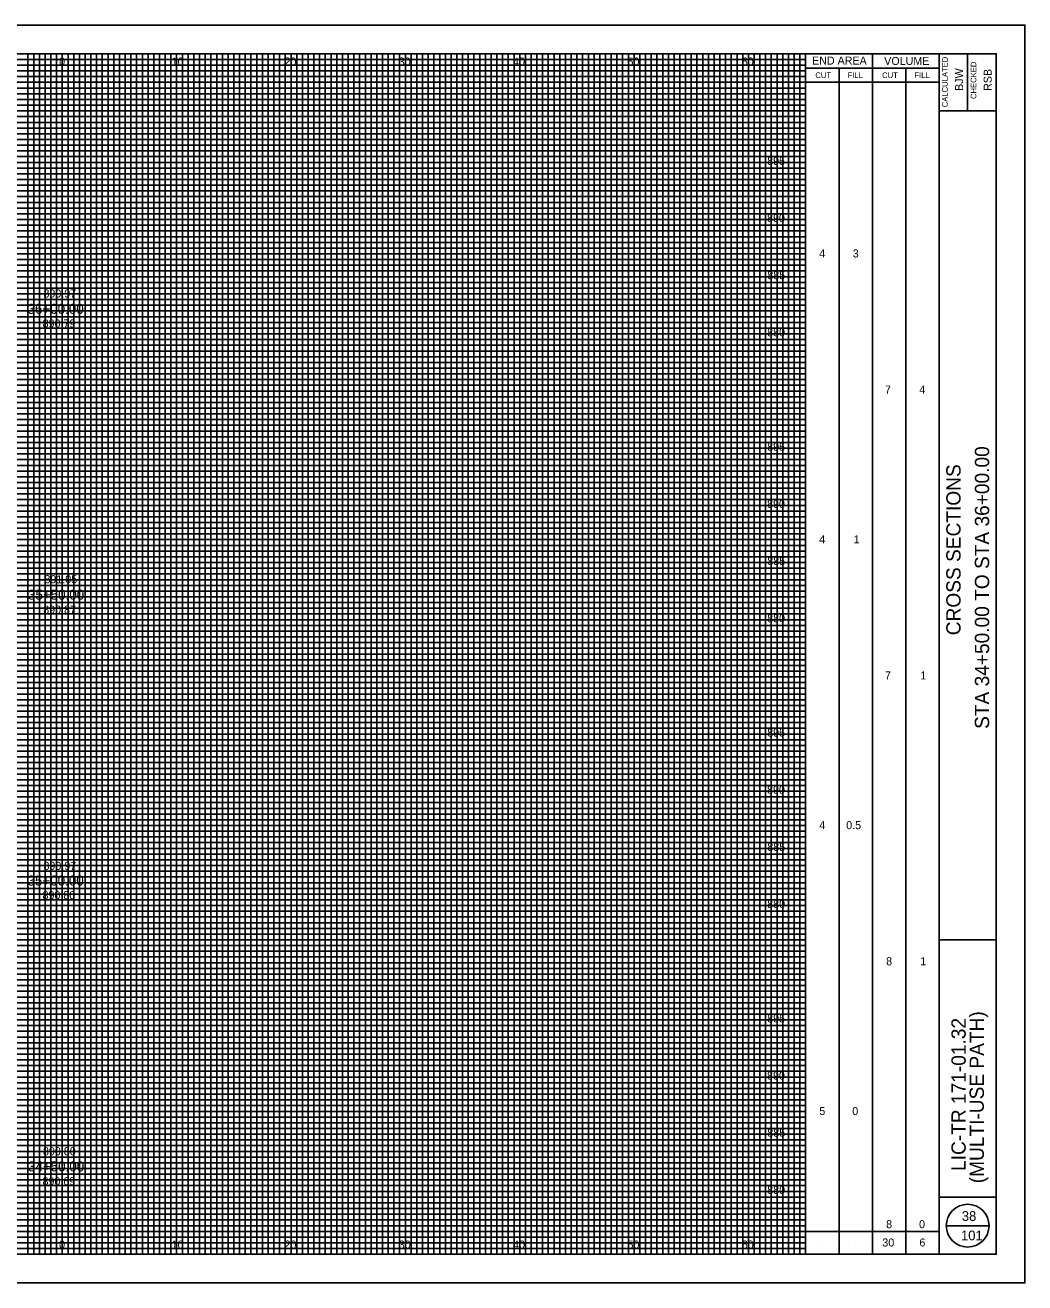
# Model space of a CAD drawing. Extents: x -10 to 160, y -2 to 2522.
# Drawn here: x 72.6 to 160, y 1147.5 to 1257.5 of the extents above; entities that cross this region are included whole.
import ezdxf

# ---------------------------------------------------------------- set-up
doc = ezdxf.new("R2010")
doc.units = 0
for name, color, linetype in [('GK_Cells', 7, 'Continuous'), ('GK_Patterns', 7, 'Continuous'), ('TX_P_10', 7, 'Continuous'), ('TX_X_10', 7, 'Continuous'), ('XS_P_Finished_Grade_Seeded', 7, 'Continuous'), ('XS_P_Pavt_Surface', 7, 'Continuous'), ('XS_P_Subgrade', 7, 'Continuous'), ('XS_X_Ground_Line', 7, 'Continuous')]:
    doc.layers.add(name, color=color, linetype=linetype)

msp = doc.modelspace()

# ---------------------------------------------------------------- linework, layer by layer
at = {"layer": 'GK_Cells'}
msp.add_lwpolyline([(-10, 1147.5), (160, 1147.5), (160, 1257.5), (-10, 1257.5)], close=True, dxfattribs=at)
at = {"layer": 'TX_P_10'}
for p, q in [((140.83, 1150), (140.83, 1255)), ((146.67, 1150), (146.67, 1255)), ((140.83, 1253.75), (152.5, 1253.75)), ((143.75, 1150), (143.75, 1253.75)), ((149.58, 1150), (149.58, 1253.75)), ((140.83, 1252.5), (152.5, 1252.5)), ((140.83, 1152), (152.5, 1152)), ((153.12, 1152.5), (156.88, 1152.5)), ((142.29, 1151), (142.29, 1151)), ((145.21, 1151), (145.21, 1151)), ((148.12, 1151), (148.12, 1151)), ((151.04, 1151), (151.04, 1151))]:
    msp.add_line(p, q, dxfattribs=at)
msp.add_circle((155, 1152.5), 1.87, dxfattribs=at)
at = {"layer": 'TX_X_10'}
for p, q in [((75.83, 1150), (75.83, 1255)), ((80.83, 1150), (80.83, 1255)), ((85.83, 1150), (85.83, 1255)), ((90.83, 1150), (90.83, 1255)), ((95.83, 1150), (95.83, 1255)), ((100.83, 1150), (100.83, 1255)), ((105.83, 1150), (105.83, 1255)), ((110.83, 1150), (110.83, 1255)), ((115.83, 1150), (115.83, 1255)), ((120.83, 1150), (120.83, 1255)), ((125.83, 1150), (125.83, 1255)), ((130.83, 1150), (130.83, 1255)), ((135.83, 1150), (135.83, 1255)), ((5.83, 1250), (140.83, 1250)), ((5.83, 1245), (140.83, 1245)), ((5.83, 1240), (140.83, 1240)), ((5.83, 1235), (140.83, 1235)), ((5.83, 1230), (140.83, 1230)), ((5.83, 1225), (140.83, 1225)), ((5.83, 1220), (140.83, 1220)), ((5.83, 1215), (140.83, 1215)), ((5.83, 1210), (140.83, 1210)), ((5.83, 1205), (140.83, 1205)), ((5.83, 1200), (140.83, 1200)), ((5.83, 1195), (140.83, 1195)), ((5.83, 1190), (140.83, 1190)), ((5.83, 1185), (140.83, 1185)), ((5.83, 1180), (140.83, 1180)), ((5.83, 1175), (140.83, 1175)), ((5.83, 1170), (140.83, 1170)), ((5.83, 1165), (140.83, 1165)), ((5.83, 1160), (140.83, 1160)), ((5.83, 1155), (140.83, 1155))]:
    msp.add_line(p, q, dxfattribs=at)
at = {"layer": 'XS_P_Pavt_Surface'}
for p, q in [((152.5, 1150), (152.5, 1255)), ((155, 1255), (155, 1250)), ((152.5, 1250), (157.5, 1250)), ((152.5, 1177.5), (157.5, 1177.5)), ((152.5, 1155), (157.5, 1155))]:
    msp.add_line(p, q, dxfattribs=at)
msp.add_lwpolyline([(0, 1255), (157.5, 1255), (157.5, 1150), (0, 1150)], close=True, dxfattribs=at)
at = {"layer": 'XS_X_Ground_Line'}
for p, q in [((5.83, 1254.5), (140.83, 1254.5)), ((5.83, 1254), (140.83, 1254)), ((72.83, 1150), (72.83, 1255)), ((73.33, 1150), (73.33, 1255)), ((73.83, 1150), (73.83, 1255)), ((74.33, 1150), (74.33, 1255)), ((74.83, 1150), (74.83, 1255)), ((75.33, 1150), (75.33, 1255)), ((76.33, 1150), (76.33, 1255)), ((76.83, 1150), (76.83, 1255)), ((77.33, 1150), (77.33, 1255)), ((77.83, 1150), (77.83, 1255)), ((78.33, 1150), (78.33, 1255)), ((78.83, 1150), (78.83, 1255)), ((79.33, 1150), (79.33, 1255)), ((79.83, 1150), (79.83, 1255)), ((80.33, 1150), (80.33, 1255)), ((81.33, 1150), (81.33, 1255)), ((81.83, 1150), (81.83, 1255)), ((82.33, 1150), (82.33, 1255)), ((82.83, 1150), (82.83, 1255)), ((83.33, 1150), (83.33, 1255)), ((83.83, 1150), (83.83, 1255)), ((84.33, 1150), (84.33, 1255)), ((84.83, 1150), (84.83, 1255)), ((85.33, 1150), (85.33, 1255)), ((86.33, 1150), (86.33, 1255)), ((86.83, 1150), (86.83, 1255)), ((87.33, 1150), (87.33, 1255)), ((87.83, 1150), (87.83, 1255)), ((88.33, 1150), (88.33, 1255)), ((88.83, 1150), (88.83, 1255)), ((89.33, 1150), (89.33, 1255)), ((89.83, 1150), (89.83, 1255)), ((90.33, 1150), (90.33, 1255)), ((91.33, 1150), (91.33, 1255)), ((91.83, 1150), (91.83, 1255)), ((92.33, 1150), (92.33, 1255)), ((92.83, 1150), (92.83, 1255)), ((93.33, 1150), (93.33, 1255)), ((93.83, 1150), (93.83, 1255)), ((94.33, 1150), (94.33, 1255)), ((94.83, 1150), (94.83, 1255)), ((95.33, 1150), (95.33, 1255)), ((96.33, 1150), (96.33, 1255)), ((96.83, 1150), (96.83, 1255)), ((97.33, 1150), (97.33, 1255)), ((97.83, 1150), (97.83, 1255)), ((98.33, 1150), (98.33, 1255)), ((98.83, 1150), (98.83, 1255)), ((99.33, 1150), (99.33, 1255)), ((99.83, 1150), (99.83, 1255)), ((100.33, 1150), (100.33, 1255)), ((101.33, 1150), (101.33, 1255)), ((101.83, 1150), (101.83, 1255)), ((102.33, 1150), (102.33, 1255)), ((102.83, 1150), (102.83, 1255)), ((103.33, 1150), (103.33, 1255)), ((103.83, 1150), (103.83, 1255)), ((104.33, 1150), (104.33, 1255)), ((104.83, 1150), (104.83, 1255)), ((105.33, 1150), (105.33, 1255)), ((106.33, 1150), (106.33, 1255)), ((106.83, 1150), (106.83, 1255)), ((107.33, 1150), (107.33, 1255)), ((107.83, 1150), (107.83, 1255)), ((108.33, 1150), (108.33, 1255)), ((108.83, 1150), (108.83, 1255)), ((109.33, 1150), (109.33, 1255)), ((109.83, 1150), (109.83, 1255)), ((110.33, 1150), (110.33, 1255)), ((111.33, 1150), (111.33, 1255)), ((111.83, 1150), (111.83, 1255)), ((112.33, 1150), (112.33, 1255)), ((112.83, 1150), (112.83, 1255)), ((113.33, 1150), (113.33, 1255)), ((113.83, 1150), (113.83, 1255)), ((114.33, 1150), (114.33, 1255)), ((114.83, 1150), (114.83, 1255)), ((115.33, 1150), (115.33, 1255)), ((116.33, 1150), (116.33, 1255)), ((116.83, 1150), (116.83, 1255)), ((117.33, 1150), (117.33, 1255)), ((117.83, 1150), (117.83, 1255)), ((118.33, 1150), (118.33, 1255)), ((118.83, 1150), (118.83, 1255)), ((119.33, 1150), (119.33, 1255)), ((119.83, 1150), (119.83, 1255)), ((120.33, 1150), (120.33, 1255)), ((121.33, 1150), (121.33, 1255)), ((121.83, 1150), (121.83, 1255)), ((122.33, 1150), (122.33, 1255)), ((122.83, 1150), (122.83, 1255)), ((123.33, 1150), (123.33, 1255)), ((123.83, 1150), (123.83, 1255)), ((124.33, 1150), (124.33, 1255)), ((124.83, 1150), (124.83, 1255)), ((125.33, 1150), (125.33, 1255)), ((126.33, 1150), (126.33, 1255)), ((126.83, 1150), (126.83, 1255)), ((127.33, 1150), (127.33, 1255)), ((127.83, 1150), (127.83, 1255)), ((128.33, 1150), (128.33, 1255)), ((128.83, 1150), (128.83, 1255)), ((129.33, 1150), (129.33, 1255)), ((129.83, 1150), (129.83, 1255)), ((130.33, 1150), (130.33, 1255)), ((131.33, 1150), (131.33, 1255)), ((131.83, 1150), (131.83, 1255)), ((132.33, 1150), (132.33, 1255)), ((132.83, 1150), (132.83, 1255)), ((133.33, 1150), (133.33, 1255)), ((133.83, 1150), (133.83, 1255)), ((134.33, 1150), (134.33, 1255)), ((134.83, 1150), (134.83, 1255)), ((135.33, 1150), (135.33, 1255)), ((136.33, 1150), (136.33, 1255)), ((136.83, 1150), (136.83, 1255)), ((137.33, 1150), (137.33, 1255)), ((137.83, 1150), (137.83, 1255)), ((138.33, 1150), (138.33, 1255)), ((138.83, 1150), (138.83, 1255)), ((139.33, 1150), (139.33, 1255)), ((139.83, 1150), (139.83, 1255)), ((140.33, 1150), (140.33, 1255)), ((5.83, 1253.5), (140.83, 1253.5)), ((5.83, 1253), (140.83, 1253)), ((5.83, 1252.5), (140.83, 1252.5)), ((5.83, 1252), (140.83, 1252)), ((5.83, 1251.5), (140.83, 1251.5)), ((5.83, 1251), (140.83, 1251)), ((5.83, 1250.5), (140.83, 1250.5)), ((5.83, 1249.5), (140.83, 1249.5)), ((5.83, 1249), (140.83, 1249)), ((5.83, 1248.5), (140.83, 1248.5)), ((5.83, 1248), (140.83, 1248)), ((5.83, 1247.5), (140.83, 1247.5)), ((5.83, 1247), (140.83, 1247)), ((5.83, 1246.5), (140.83, 1246.5)), ((5.83, 1246), (140.83, 1246)), ((5.83, 1245.5), (140.83, 1245.5)), ((5.83, 1244.5), (140.83, 1244.5)), ((5.83, 1244), (140.83, 1244)), ((5.83, 1243.5), (140.83, 1243.5)), ((5.83, 1243), (140.83, 1243)), ((5.83, 1242.5), (140.83, 1242.5)), ((5.83, 1242), (140.83, 1242)), ((5.83, 1241.5), (140.83, 1241.5)), ((5.83, 1241), (140.83, 1241)), ((5.83, 1240.5), (140.83, 1240.5)), ((5.83, 1239.5), (140.83, 1239.5)), ((5.83, 1239), (140.83, 1239)), ((5.83, 1238.5), (140.83, 1238.5)), ((5.83, 1238), (140.83, 1238)), ((5.83, 1237.5), (140.83, 1237.5)), ((5.83, 1237), (140.83, 1237)), ((5.83, 1236.5), (140.83, 1236.5)), ((5.83, 1236), (140.83, 1236)), ((5.83, 1235.5), (140.83, 1235.5)), ((5.83, 1234.5), (140.83, 1234.5)), ((5.83, 1234), (140.83, 1234)), ((5.83, 1233.5), (140.83, 1233.5)), ((5.83, 1233), (140.83, 1233)), ((5.83, 1232.5), (140.83, 1232.5)), ((5.83, 1232), (140.83, 1232)), ((5.83, 1231.5), (140.83, 1231.5)), ((5.83, 1231), (140.83, 1231)), ((5.83, 1230.5), (140.83, 1230.5)), ((5.83, 1229.5), (140.83, 1229.5)), ((5.83, 1229), (140.83, 1229)), ((5.83, 1228.5), (140.83, 1228.5)), ((5.83, 1228), (140.83, 1228)), ((5.83, 1227.5), (140.83, 1227.5)), ((5.83, 1227), (140.83, 1227)), ((5.83, 1226.5), (140.83, 1226.5)), ((5.83, 1226), (140.83, 1226)), ((5.83, 1225.5), (140.83, 1225.5)), ((5.83, 1224.5), (140.83, 1224.5)), ((5.83, 1224), (140.83, 1224)), ((5.83, 1223.5), (140.83, 1223.5)), ((5.83, 1223), (140.83, 1223)), ((5.83, 1222.5), (140.83, 1222.5)), ((5.83, 1222), (140.83, 1222)), ((5.83, 1221.5), (140.83, 1221.5)), ((5.83, 1221), (140.83, 1221)), ((5.83, 1220.5), (140.83, 1220.5)), ((5.83, 1219.5), (140.83, 1219.5)), ((5.83, 1219), (140.83, 1219)), ((5.83, 1218.5), (140.83, 1218.5)), ((5.83, 1218), (140.83, 1218)), ((5.83, 1217.5), (140.83, 1217.5)), ((5.83, 1217), (140.83, 1217)), ((5.83, 1216.5), (140.83, 1216.5)), ((5.83, 1216), (140.83, 1216)), ((5.83, 1215.5), (140.83, 1215.5)), ((5.83, 1214.5), (140.83, 1214.5)), ((5.83, 1214), (140.83, 1214)), ((5.83, 1213.5), (140.83, 1213.5)), ((5.83, 1213), (140.83, 1213)), ((5.83, 1212.5), (140.83, 1212.5)), ((5.83, 1212), (140.83, 1212)), ((5.83, 1211.5), (140.83, 1211.5)), ((5.83, 1211), (140.83, 1211)), ((5.83, 1210.5), (140.83, 1210.5)), ((5.83, 1209.5), (140.83, 1209.5)), ((5.83, 1209), (140.83, 1209)), ((5.83, 1208.5), (140.83, 1208.5)), ((5.83, 1208), (140.83, 1208)), ((5.83, 1207.5), (140.83, 1207.5)), ((5.83, 1207), (140.83, 1207)), ((5.83, 1206.5), (140.83, 1206.5)), ((5.83, 1206), (140.83, 1206)), ((5.83, 1205.5), (140.83, 1205.5)), ((5.83, 1204.5), (140.83, 1204.5)), ((5.83, 1204), (140.83, 1204)), ((5.83, 1203.5), (140.83, 1203.5)), ((5.83, 1203), (140.83, 1203)), ((5.83, 1202.5), (140.83, 1202.5)), ((5.83, 1202), (140.83, 1202)), ((5.83, 1201.5), (140.83, 1201.5)), ((5.83, 1201), (140.83, 1201)), ((5.83, 1200.5), (140.83, 1200.5)), ((5.83, 1199.5), (140.83, 1199.5)), ((5.83, 1199), (140.83, 1199)), ((5.83, 1198.5), (140.83, 1198.5)), ((5.83, 1198), (140.83, 1198)), ((5.83, 1197.5), (140.83, 1197.5)), ((5.83, 1197), (140.83, 1197)), ((5.83, 1196.5), (140.83, 1196.5)), ((5.83, 1196), (140.83, 1196)), ((5.83, 1195.5), (140.83, 1195.5)), ((5.83, 1194.5), (140.83, 1194.5)), ((5.83, 1194), (140.83, 1194)), ((5.83, 1193.5), (140.83, 1193.5)), ((5.83, 1193), (140.83, 1193)), ((5.83, 1192.5), (140.83, 1192.5)), ((5.83, 1192), (140.83, 1192)), ((5.83, 1191.5), (140.83, 1191.5)), ((5.83, 1191), (140.83, 1191)), ((5.83, 1190.5), (140.83, 1190.5)), ((5.83, 1189.5), (140.83, 1189.5)), ((5.83, 1189), (140.83, 1189)), ((5.83, 1188.5), (140.83, 1188.5)), ((5.83, 1188), (140.83, 1188)), ((5.83, 1187.5), (140.83, 1187.5)), ((5.83, 1187), (140.83, 1187)), ((5.83, 1186.5), (140.83, 1186.5)), ((5.83, 1186), (140.83, 1186)), ((5.83, 1185.5), (140.83, 1185.5)), ((5.83, 1184.5), (140.83, 1184.5)), ((5.83, 1184), (140.83, 1184)), ((5.83, 1183.5), (140.83, 1183.5)), ((5.83, 1183), (140.83, 1183)), ((5.83, 1182.5), (140.83, 1182.5)), ((5.83, 1182), (140.83, 1182)), ((5.83, 1181.5), (140.83, 1181.5)), ((5.83, 1181), (140.83, 1181)), ((5.83, 1180.5), (140.83, 1180.5)), ((5.83, 1179.5), (140.83, 1179.5)), ((5.83, 1179), (140.83, 1179)), ((5.83, 1178.5), (140.83, 1178.5)), ((5.83, 1178), (140.83, 1178)), ((5.83, 1177.5), (140.83, 1177.5)), ((5.83, 1177), (140.83, 1177)), ((5.83, 1176.5), (140.83, 1176.5)), ((5.83, 1176), (140.83, 1176)), ((5.83, 1175.5), (140.83, 1175.5)), ((5.83, 1174.5), (140.83, 1174.5)), ((5.83, 1174), (140.83, 1174)), ((5.83, 1173.5), (140.83, 1173.5)), ((5.83, 1173), (140.83, 1173)), ((5.83, 1172.5), (140.83, 1172.5)), ((5.83, 1172), (140.83, 1172)), ((5.83, 1171.5), (140.83, 1171.5)), ((5.83, 1171), (140.83, 1171)), ((5.83, 1170.5), (140.83, 1170.5)), ((5.83, 1169.5), (140.83, 1169.5)), ((5.83, 1169), (140.83, 1169)), ((5.83, 1168.5), (140.83, 1168.5)), ((5.83, 1168), (140.83, 1168)), ((5.83, 1167.5), (140.83, 1167.5)), ((5.83, 1167), (140.83, 1167)), ((5.83, 1166.5), (140.83, 1166.5)), ((5.83, 1166), (140.83, 1166)), ((5.83, 1165.5), (140.83, 1165.5)), ((5.83, 1164.5), (140.83, 1164.5)), ((5.83, 1164), (140.83, 1164)), ((5.83, 1163.5), (140.83, 1163.5)), ((5.83, 1163), (140.83, 1163)), ((5.83, 1162.5), (140.83, 1162.5)), ((5.83, 1162), (140.83, 1162)), ((5.83, 1161.5), (140.83, 1161.5)), ((5.83, 1161), (140.83, 1161)), ((5.83, 1160.5), (140.83, 1160.5)), ((5.83, 1159.5), (140.83, 1159.5)), ((5.83, 1159), (140.83, 1159)), ((5.83, 1158.5), (140.83, 1158.5)), ((5.83, 1158), (140.83, 1158)), ((5.83, 1157.5), (140.83, 1157.5)), ((5.83, 1157), (140.83, 1157)), ((5.83, 1156.5), (140.83, 1156.5)), ((5.83, 1156), (140.83, 1156)), ((5.83, 1155.5), (140.83, 1155.5)), ((5.83, 1154.5), (140.83, 1154.5)), ((5.83, 1154), (140.83, 1154)), ((5.83, 1153.5), (140.83, 1153.5)), ((5.83, 1153), (140.83, 1153)), ((5.83, 1152.5), (140.83, 1152.5)), ((5.83, 1152), (140.83, 1152)), ((5.83, 1151.5), (140.83, 1151.5)), ((5.83, 1151), (140.83, 1151)), ((5.83, 1150.5), (140.83, 1150.5))]:
    msp.add_line(p, q, dxfattribs=at)

# ---------------------------------------------------------------- texts
at = {"layer": 'GK_Patterns'}
for s, height, p in [('0', 0.7, (75.55, 1253.97)), ('0', 0.7, (75.55, 1253.97)), ('10', 0.7, (85.39, 1253.97)), ('20', 0.7, (95.26, 1253.97)), ('30', 0.7, (105.25, 1253.97)), ('40', 0.7, (115.25, 1253.97)), ('50', 0.7, (125.25, 1253.97)), ('60', 0.7, (135.25, 1253.97)), ('895', 0.7, (137.47, 1245.28)), ('890', 0.7, (137.46, 1240.28)), ('4', 0.7, (142.02, 1237.18)), ('3', 0.7, (144.95, 1237.18)), ('885', 0.7, (137.48, 1235.28)), ('36+00.00', 0.875, (72.79, 1232.25)), ('880', 0.7, (137.47, 1230.28)), ('7', 0.7, (147.77, 1225.28)), ('4', 0.7, (150.77, 1225.28)), ('895', 0.7, (137.47, 1220.28)), ('890', 0.7, (137.46, 1215.28)), ('4', 0.7, (142.02, 1212.18)), ('1', 0.7, (145.03, 1212.18)), ('885', 0.7, (137.48, 1210.28)), ('35+50.00', 0.875, (72.83, 1207.25)), ('880', 0.7, (137.47, 1205.28)), ('7', 0.7, (147.77, 1200.28)), ('1', 0.7, (150.86, 1200.28)), ('895', 0.7, (137.47, 1195.28)), ('890', 0.7, (137.46, 1190.28)), ('4', 0.7, (142.02, 1187.18)), ('0.5', 0.7, (144.38, 1187.18)), ('885', 0.7, (137.48, 1185.28)), ('35+00.00', 0.875, (72.79, 1182.25)), ('880', 0.7, (137.47, 1180.28)), ('8', 0.7, (147.87, 1175.28)), ('1', 0.7, (150.86, 1175.28)), ('895', 0.7, (137.47, 1170.28)), ('890', 0.7, (137.46, 1165.28)), ('5', 0.7, (142.03, 1162.18)), ('0', 0.7, (144.91, 1162.18)), ('885', 0.7, (137.48, 1160.28)), ('34+50.00', 0.875, (72.83, 1157.25)), ('880', 0.7, (137.47, 1155.28)), ('8', 0.7, (147.87, 1152.28)), ('0', 0.7, (150.75, 1152.28)), ('0', 0.7, (75.55, 1150.5)), ('0', 0.7, (75.55, 1150.5)), ('10', 0.7, (85.39, 1150.5)), ('20', 0.7, (95.26, 1150.5)), ('30', 0.7, (105.25, 1150.5)), ('40', 0.7, (115.25, 1150.5)), ('50', 0.7, (125.25, 1150.5)), ('60', 0.7, (135.25, 1150.5)), ('30', 0.7, (147.54, 1150.68)), ('6', 0.7, (150.78, 1150.68))]:
    msp.add_text(s, height=height, dxfattribs=at).set_placement(p)
at = {"layer": 'TX_P_10'}
for s, height, p in [('END AREA', 0.7, (141.39, 1254.05)), ('VOLUME', 0.7, (147.7, 1254.02)), ('CUT', 0.5, (141.68, 1252.87)), ('FILL', 0.5, (144.5, 1252.87)), ('CUT', 0.5, (147.52, 1252.87)), ('FILL', 0.5, (150.34, 1252.87)), ('38', 0.85, (154.49, 1152.92)), ('101', 0.85, (154.42, 1151.22))]:
    msp.add_text(s, height=height, dxfattribs=at).set_placement(p)
for s, height, p in [('CALCULATED', 0.5, (153.26, 1250.32)), ('CHECKED', 0.5, (155.76, 1251.04)), ('BJW', 0.7, (154.6, 1251.75)), ('RSB', 0.7, (157.1, 1251.75)), ('STA 34+50.00 TO STA 36+00.00', 1.25, (156.88, 1195.95)), ('CROSS SECTIONS', 1.25, (154.38, 1204.14)), ('LIC-TR 171-01.32', 1.25, (154.83, 1157.29)), ('(MULTI-USE PATH)', 1.25, (156.42, 1156.21))]:
    msp.add_text(s, height=height, rotation=90, dxfattribs=at).set_placement(p)
at = {"layer": 'XS_P_Finished_Grade_Seeded'}
for s, p in [('890.79', (74.11, 1231.06)), ('890.87', (74.16, 1206.03)), ('890.80', (74.1, 1181.06)), ('890.69', (74.1, 1156.04))]:
    msp.add_text(s, height=0.7, dxfattribs=at).set_placement(p)
at = {"layer": 'XS_P_Subgrade'}
for s, p in [('890.97', (74.18, 1233.68)), ('891.05', (74.27, 1208.69)), ('890.97', (74.18, 1183.62)), ('890.80', (74.14, 1158.66))]:
    msp.add_text(s, height=0.7, dxfattribs=at).set_placement(p)

doc.saveas('drawing.dxf')
